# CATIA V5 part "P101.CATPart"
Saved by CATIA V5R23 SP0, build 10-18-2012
Part number: 05-LICP-T02-E-S07-P101
Definition: Pignon A Chaine Menant
Description: Pignon A Chaine Menant
Bounding box of the stored display mesh (mm): x 0 to 6.5, y -29.854 to 29.854, z -29.854 to 29.854
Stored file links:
  C:\wamp\www\COURS\CONCEPTION GMP1\TITRE 02-SEMESTRE 2\03-TP7-PRESSE MECANIQUE\eleve\P101.CATPart
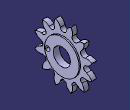
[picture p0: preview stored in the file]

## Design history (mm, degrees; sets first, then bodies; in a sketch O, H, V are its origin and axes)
Body1 (main body)
  Sketch1 on yz-plane, origin (0, 0, 0), H (0, 1, 0), V (0, 0, 1)
    construction circle A1 centre (0, 0) radius 24.5345
    construction line L1 (0, 0) -> (0, 34.5291)
    construction line L2 (0, 0) -> (-17.2645, 29.9031)
    construction line L3 (0.4087, -0.2231) -> (-29.502, 17.0281)
    construction line L4 (0.4655, 0.0111) -> (-34.0636, -0.0042)
    construction line L5 (0.3976, 0.2423) -> (-29.4978, -17.0355)
    construction line L6 (-33.8588, -8.8396) -> (-3.921, -26.0438)
    construction line L7 (-0.0111, 0.4655) -> (0.0042, -34.0636)
    construction line L8 (-0.2423, 0.3976) -> (17.0355, -29.4978)
    construction line L9 (-0.4087, 0.2231) -> (29.502, -17.0281)
    construction line L10 (-0.4655, -0.0111) -> (34.0636, 0.0042)
    construction line L11 (-0.3976, -0.2423) -> (29.4978, 17.0355)
    construction line L12 (0, 0) -> (17.2645, 29.9031)
    construction line L13 (0, 0) -> (0, 34.5291)
    arc A2 centre (0, 24.5345) radius 3.175 from (-3.1683, 24.3291) to (3.1683, 24.3291) ccw
    point P26 (0, 24.5345)
    arc A3 centre (-12.2673, 21.2475) radius 3.175 from (-14.9084, 19.4854) to (-9.4207, 22.6538) ccw
    point P27 (-12.2673, 21.2475)
    arc A4 centre (-21.2475, 12.2673) radius 3.175 from (-22.6538, 9.4207) to (-19.4854, 14.9084) ccw
    point P28 (-21.2475, 12.2673)
    arc A5 centre (-24.5345, 0) radius 3.175 from (-24.3291, -3.1683) to (-24.3291, 3.1683) ccw
    point P29 (-24.5345, 0)
    arc A6 centre (-21.2475, -12.2673) radius 3.175 from (-19.4854, -14.9084) to (-22.6538, -9.4207) ccw
    point P30 (-21.2475, -12.2673)
    arc A7 centre (-12.2673, -21.2475) radius 3.175 from (-9.0989, -21.453) to (-14.9084, -19.4854) ccw
    point P31 (-12.2673, -21.2475)
    arc A8 centre (0, -24.5345) radius 3.175 from (3.1683, -24.3291) to (-3.1683, -24.3291) ccw
    point P32 (0, -24.5345)
    arc A9 centre (12.2673, -21.2475) radius 3.175 from (14.9084, -19.4854) to (9.4207, -22.6538) ccw
    point P33 (12.2673, -21.2475)
    arc A10 centre (21.2475, -12.2673) radius 3.175 from (22.6538, -9.4207) to (19.4854, -14.9084) ccw
    point P34 (21.2475, -12.2673)
    arc A11 centre (24.5345, 0) radius 3.175 from (24.3291, 3.1683) to (24.3291, -3.1683) ccw
    point P35 (24.5345, 0)
    arc A12 centre (21.2475, 12.2673) radius 3.175 from (19.4854, 14.9084) to (22.6538, 9.4207) ccw
    point P36 (21.2475, 12.2673)
    arc A13 centre (12.2673, 21.2475) radius 3.175 from (9.4207, 22.6538) to (14.9084, 19.4854) ccw
    point P37 (12.2673, 21.2475)
    point P38 (-3.1683, 24.3291)
    arc A14 centre (0, 24.5345) radius 9.6066 from (9.4207, 22.6538) to (7.9993, 29.854) ccw
    point P39 (-9.4207, 22.6538)
    arc A15 centre (12.2673, 21.2475) radius 9.6066 from (19.4854, 14.9084) to (21.8546, 21.8546) ccw
    point P41 (3.1683, 24.3291)
    arc A16 centre (21.2475, 12.2673) radius 9.6066 from (24.3291, 3.1683) to (29.854, 7.9993) ccw
    point P43 (14.9084, 19.4854)
    point P44 (24.3291, 3.1683)
    arc A17 centre (24.5345, 0) radius 9.6066 from (22.6538, -9.4207) to (29.854, -7.9993) ccw
    point P45 (22.6538, 9.4207)
    point P46 (22.6538, -9.4207)
    arc A18 centre (21.2475, -12.2673) radius 9.6066 from (14.9084, -19.4854) to (21.8546, -21.8546) ccw
    point P47 (24.3291, -3.1683)
    point P48 (14.9084, -19.4854)
    arc A19 centre (12.2673, -21.2475) radius 9.6066 from (3.1683, -24.3291) to (7.9993, -29.854) ccw
    point P49 (19.4854, -14.9084)
    point P50 (3.1683, -24.3291)
    arc A20 centre (0, -24.5345) radius 9.6066 from (-9.0989, -21.453) to (-7.9993, -29.854) ccw
    point P51 (9.4207, -22.6538)
    arc A21 centre (-12.2673, -21.2475) radius 9.6066 from (-19.4854, -14.9084) to (-21.8546, -21.8546) ccw
    point P53 (-12.2673, -21.2475)
    point P54 (-3.1683, -24.3291)
    point P55 (-19.4854, -14.9084)
    arc A22 centre (-21.2475, -12.2673) radius 9.6066 from (-24.3291, -3.1683) to (-29.854, -7.9993) ccw
    point P56 (-14.9084, -19.4854)
    point P57 (-24.3291, -3.1683)
    arc A23 centre (-24.5345, 0) radius 9.6066 from (-22.6538, 9.4207) to (-29.854, 7.9993) ccw
    point P58 (-22.6538, -9.4207)
    point P59 (-22.6538, 9.4207)
    arc A24 centre (-21.2475, 12.2673) radius 9.6066 from (-14.9084, 19.4854) to (-21.8546, 21.8546) ccw
    point P60 (-24.3291, 3.1683)
    arc A25 centre (-12.2673, 21.2475) radius 9.6066 from (-3.1683, 24.3291) to (-7.9993, 29.854) ccw
    point P62 (-19.4854, 14.9084)
    point P63 (7.9993, 29.854)
    arc A26 centre (0, 24.5345) radius 9.6066 from (-7.9993, 29.854) to (-9.4207, 22.6538) ccw
    arc A27 centre (-12.2673, 21.2475) radius 9.6066 from (-21.8546, 21.8546) to (-19.4854, 14.9084) ccw
    arc A28 centre (-21.2475, 12.2673) radius 9.6066 from (-29.854, 7.9993) to (-24.3291, 3.1683) ccw
    arc A29 centre (-24.5345, 0) radius 9.6066 from (-29.854, -7.9993) to (-22.6538, -9.4207) ccw
    arc A30 centre (-21.2475, -12.2673) radius 9.6066 from (-21.8546, -21.8546) to (-14.9084, -19.4854) ccw
    arc A31 centre (-12.2673, -21.2475) radius 9.6066 from (-7.9993, -29.854) to (-3.1683, -24.3291) ccw
    point P70 (7.9993, -29.854)
    arc A32 centre (12.2673, -21.2475) radius 9.6066 from (21.8546, -21.8546) to (19.4854, -14.9084) ccw
    arc A33 centre (0, -24.5345) radius 9.6066 from (7.9993, -29.854) to (9.4207, -22.6538) ccw
    arc A34 centre (21.2475, -12.2673) radius 9.6066 from (29.854, -7.9993) to (24.3291, -3.1683) ccw
    arc A35 centre (24.5345, 0) radius 9.6066 from (29.854, 7.9993) to (22.6538, 9.4207) ccw
    arc A36 centre (21.2475, 12.2673) radius 9.6066 from (21.8546, 21.8546) to (14.9084, 19.4854) ccw
    arc A37 centre (12.2673, 21.2475) radius 9.6066 from (7.9993, 29.854) to (3.1683, 24.3291) ccw
    point P75 (22.6538, 9.4207)
    point P76 (24.3291, 3.1683)
    point P77 (24.3291, -3.1683)
    point P78 (22.6538, -9.4207)
    point P79 (19.4854, -14.9084)
    point P80 (14.9084, -19.4854)
    point P81 (3.1683, -24.3291)
    point P82 (-3.1683, -24.3291)
    point P83 (-14.9084, -19.4854)
    point P84 (-19.4854, -14.9084)
    point P85 (-22.6538, -9.4207)
    point P86 (-24.3291, -3.1683)
    point P87 (-24.3291, 3.1683)
    point P88 (-19.4854, 14.9084)
    point P89 (-3.1683, 24.3291)
    radius A2 = 3.175
    radius A3 = 3.175
    angle L2 L13 = 30
    radius A13 = 3.175
    radius A12 = 3.175
    radius A11 = 3.175
    radius A10 = 3.175
    radius A4 = 3.175
    radius A5 = 3.175
    radius A6 = 3.175
    radius A7 = 3.175
    radius A8 = 3.175
    radius A9 = 3.175
    distance P37 P36 = 12.7
    distance P36 P35 = 12.7
    distance P35 P34 = 12.7
    distance P34 P33 = 12.7
    distance P37 P26 = 12.7
    distance P26 P27 = 12.7
    distance P27 P28 = 12.7
    distance P28 P29 = 12.7
    distance P53 P30 = 12.7
    distance P32 P33 = 12.7
    distance P30 P29 = 12.7 (reference)
    distance P32 P53 = 12.7 (reference)
    radius A1 = 24.5345 (reference)
    vertical: L1 V
    coincidence: P26 L1, P26 A1, A1 P27, P28 L3, P28 A1, P29 L4, P29 A1, P30 L5, P30 A1, P31 L6, P31 A1, P32 L7, P32 A1, P33 L8, P33 A1, P34 L9, P34 A1, P35 L10, P35 A1, P36 L11, P36 A1, P37 A1, P38 A1, P39 A1, P41 A1, P43 A1, P44 A1, P45 A12, P45 A1, P46 A10, P47 A11, P47 A1, P48 A9, P49 A10, P49 A1, P50 A8, P51 A1, P53 L6, P53 A1, P54 A8, P54 A1, P55 A1, P56 A7, P56 A1, P57 A5, P58 A6, P58 A1, P60 A5, P60 A1, P62 A4, P62 A1, A15 P63, A14 A26, A25 A27, A24 A28, A23 A29, A22 A30, A21 A31, A20 P70, A19 A32, A20 A33, A18 A34, A17 A35, A16 A36, A15 A37, A1 P75, A1 P76, A1 P77, A1 P78, A1 P79, A1 P80, A1 P81, A1 P82, A1 P83, A1 P84, A1 P85, A1 P86, A1 P87, A1 P88, A1 P89, P54 P82, P55 P84, P58 P85, P60 P87, P62 P88, P57 P86, P59 A1
  Pad1: profile Sketch1, direction (1, 0, 0), length 5
  Sketch2 on face of Pad1, origin (5, 0, 0), H (0, 1, 0), V (0, 0, 1)
    circle A1 centre (0, 0) radius 18
    radius A1 = 18
  Pad2: profile Sketch2, direction (1, 0, 0), length 1.5
  Sketch3 on face of Pad2, origin (6.5, 0, 0), H (0, 1, 0), V (0, 0, 1)
    point P1 (0, 0)
    reference projected circle E1 centre (0, 0) radius 18 from edge [face of Pad2 | face of Pad2]
    concentricity: P1 E1
  Hole1: placed by Sketch3, at (6.5, 0, 0) direction (-1, 0, 0), diameter 18, depth 10
  Sketch4 on face of Pad1, origin (0, -14.2317, 2.8506), H (0, 1, 0), V (0, 0, -1)
    point P1 (-0.7683, 2.8506)
    reference intersected line E1 through (0, 2.8506) direction (1, 0) from xy-plane
    reference intersected line E2 through (14.2317, 0) direction (0, 1) from zx-plane
    distance P1 E2 = 15
    coincidence: P1 E1
  Hole2: placed by Sketch4, at (0, -15, 0) direction (1, 0, 0), diameter 5, depth 10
